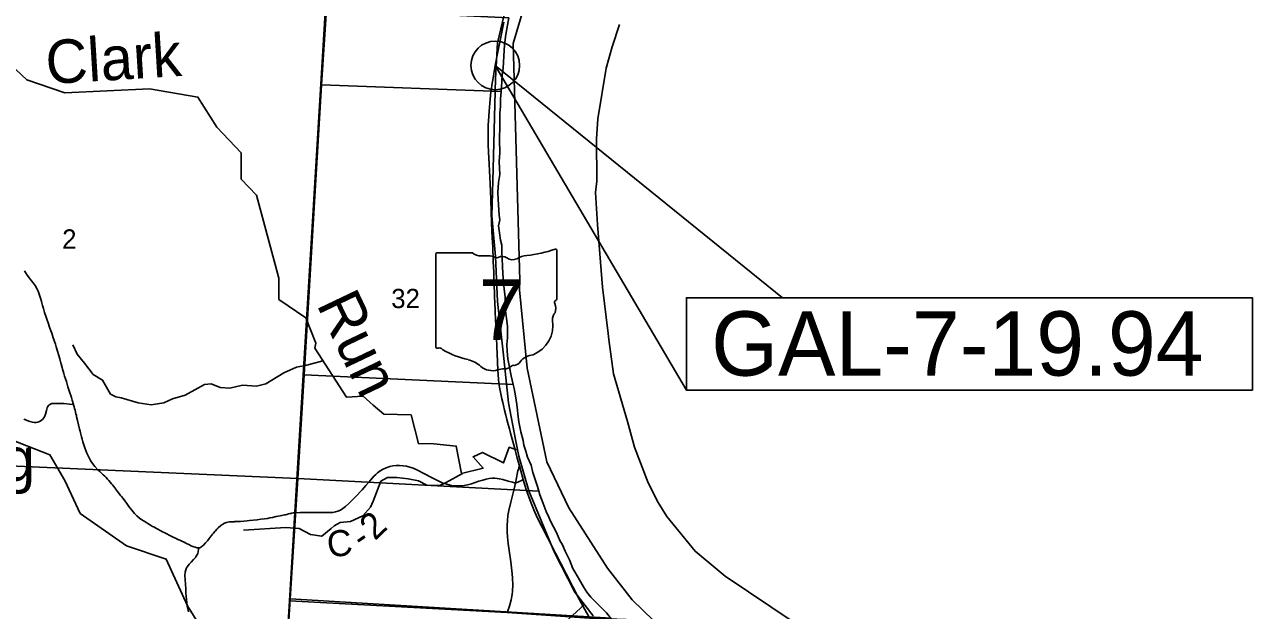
# Model space of a CAD drawing. Extents: x 0 to 34, y 0 to 22.
# Drawn here: x 26.889 to 29.562, y 16.649 to 17.925 of the extents above; entities that cross this region are included whole.
import ezdxf

# ---------------------------------------------------------------- set-up
doc = ezdxf.new("R2010")
doc.units = 0
for name, color, linetype in [('Default', 7, 'Continuous'), ('GM_X_County_Road', 7, 'Continuous'), ('GM_X_County_Road_Text', 7, 'Continuous'), ('GM_X_Interchange_Ramps', 7, 'Continuous'), ('GM_X_Major_River', 7, 'Continuous'), ('GM_X_Minor_River', 7, 'Continuous'), ('GM_X_Minor_River_Text', 7, 'Continuous'), ('GM_X_Section', 7, 'Continuous'), ('GM_X_Section_Text', 7, 'Continuous'), ('GM_X_State_Location', 7, 'Continuous'), ('GM_X_State_Route', 7, 'Continuous'), ('GM_X_State_Shield', 7, 'Continuous'), ('GM_X_Township_Road', 7, 'Continuous'), ('SH_Text', 7, 'Continuous')]:
    doc.layers.add(name, color=color, linetype=linetype)

msp = doc.modelspace()

# ---------------------------------------------------------------- linework, layer by layer
at = {"layer": 'Default'}
for points in [[(27.5436, 17.9511), (27.477, 16.8624), (27.4654, 16.67), (27.9391, 16.6444), (28.1188, 16.6326), (28.2577, 16.6271), (28.2114, 16.6724), (28.1579, 16.7413), (28.0739, 16.8728), (28.0259, 16.9726), (27.9832, 17.1768), (27.9665, 17.3472), (27.9669, 17.3673), (27.9525, 17.8831), (27.9847, 17.9912)], [(26.8866, 15.9536), (26.8953, 15.9537), (26.9051, 15.9532), (26.9173, 15.9519), (26.9205, 15.9516), (26.9254, 15.951), (26.9323, 15.9503), (26.9416, 15.9499), (26.9554, 15.9494), (26.9643, 15.9495), (26.9763, 15.9496), (26.9823, 15.9498), (26.987, 15.951), (26.9903, 15.9525), (26.9911, 15.953), (27.0939, 15.9486), (27.4201, 15.9327), (27.4654, 16.67), (27.477, 16.8624), (27.5436, 17.9511)], [(27.9391, 16.6444), (27.4654, 16.67), (27.4201, 15.9327)]]:
    msp.add_lwpolyline(points, dxfattribs=at)
at = {"layer": 'GM_X_County_Road'}
for points in [[(27.3465, 16.8425), (27.3455, 16.8424), (27.3398, 16.8422), (27.3343, 16.8418), (27.3284, 16.8405), (27.3238, 16.8389), (27.3206, 16.8373), (27.3161, 16.8342), (27.3103, 16.8288), (27.3076, 16.8258), (27.3047, 16.8223), (27.303, 16.8207), (27.3002, 16.8175), (27.2981, 16.8152), (27.2967, 16.8132), (27.2952, 16.8113), (27.2907, 16.8056), (27.2868, 16.8007), (27.2831, 16.7965), (27.2783, 16.7915), (27.2756, 16.789), (27.2739, 16.7877), (27.2724, 16.7867), (27.2701, 16.7858), (27.2681, 16.7855), (27.2667, 16.7853), (27.2647, 16.7855), (27.2623, 16.786), (27.2605, 16.7867), (27.2553, 16.7887), (27.2518, 16.7902), (27.2462, 16.7929), (27.2428, 16.7944), (27.24, 16.7958), (27.2361, 16.7976), (27.2316, 16.7997), (27.227, 16.8019), (27.2225, 16.804), (27.2192, 16.8056), (27.2136, 16.8083), (27.2092, 16.8105), (27.2025, 16.8138), (27.2003, 16.8149), (27.1954, 16.8173), (27.1927, 16.8187), (27.189, 16.8205), (27.1853, 16.8225), (27.1775, 16.8267), (27.1749, 16.8282), (27.1714, 16.8303), (27.1677, 16.8323), (27.1633, 16.8346), (27.1491, 16.8435), (27.1445, 16.8467), (27.1393, 16.8503), (27.1335, 16.855), (27.1281, 16.8602), (27.1221, 16.8674), (27.1185, 16.8721), (27.1156, 16.8758), (27.1112, 16.8818), (27.1071, 16.8876), (27.1034, 16.8928), (27.0997, 16.8973), (27.098, 16.8995), (27.0962, 16.9019), (27.0914, 16.9082), (27.087, 16.9141), (27.0858, 16.9156), (27.0824, 16.9199), (27.0805, 16.9224), (27.0785, 16.9247), (27.0755, 16.9286), (27.0722, 16.9324), (27.0695, 16.9353), (27.0667, 16.9383), (27.0633, 16.9412), (27.0601, 16.9444), (27.0566, 16.9483), (27.0527, 16.9519), (27.0487, 16.9554), (27.0418, 16.9627), (27.0367, 16.969), (27.0325, 16.9753), (27.0292, 16.9813), (27.0245, 16.9916), (27.02, 17.0032), (27.0158, 17.0163), (27.0141, 17.0222), (27.0128, 17.027), (27.0105, 17.036), (27.0096, 17.0396), (27.0086, 17.0438), (27.0042, 17.0625), (27.0023, 17.0709), (27.0017, 17.0733), (27.0007, 17.0775), (26.9988, 17.0853), (26.9978, 17.0889), (26.9968, 17.0924), (26.9956, 17.0966), (26.9953, 17.0978), (26.9924, 17.1072), (26.9908, 17.1126), (26.9893, 17.1173), (26.9875, 17.1232), (26.9856, 17.1292), (26.9834, 17.1363), (26.9817, 17.1416), (26.9799, 17.1475), (26.978, 17.1535), (26.9762, 17.1594), (26.9745, 17.1647), (26.9729, 17.17), (26.9718, 17.1742), (26.9706, 17.1783), (26.9695, 17.1823), (26.9691, 17.1839), (26.9684, 17.1861), (26.968, 17.1877), (26.9654, 17.1966), (26.958, 17.2227), (26.956, 17.229), (26.9542, 17.2345), (26.9526, 17.2391), (26.9514, 17.2426), (26.948, 17.2525), (26.9461, 17.2578), (26.9453, 17.2601), (26.9441, 17.2635), (26.9426, 17.2677), (26.9412, 17.273), (26.9374, 17.2834), (26.9352, 17.2898), (26.9325, 17.298), (26.9301, 17.3066), (26.9282, 17.3132), (26.9257, 17.3219), (26.9235, 17.3292), (26.9208, 17.338), (26.9183, 17.344), (26.916, 17.3489), (26.9118, 17.3563), (26.9079, 17.3621), (26.9042, 17.3667), (26.8999, 17.3723), (26.8948, 17.379), (26.8908, 17.3848), (26.8887, 17.3883)], [(27.9573, 16.926), (27.9507, 16.9282), (27.9415, 16.9309), (27.9303, 16.9339), (27.9223, 16.9358), (27.9173, 16.9367), (27.9124, 16.9372), (27.907, 16.9371), (27.9005, 16.9365), (27.8937, 16.935), (27.8865, 16.9331), (27.8775, 16.9303), (27.8619, 16.9248), (27.853, 16.9223), (27.8459, 16.9209), (27.8385, 16.9205), (27.8315, 16.9203), (27.8229, 16.9208), (27.8156, 16.922), (27.8084, 16.924), (27.7981, 16.9272), (27.7908, 16.9303), (27.7803, 16.9355), (27.7538, 16.9497), (27.7484, 16.9525), (27.7426, 16.9556), (27.7348, 16.9587), (27.7278, 16.961), (27.7203, 16.9631), (27.7129, 16.9641), (27.7047, 16.9648), (27.6977, 16.9647), (27.6908, 16.9638), (27.6841, 16.9623), (27.6763, 16.9597), (27.6695, 16.9567), (27.663, 16.953), (27.6569, 16.9488), (27.6532, 16.9454), (27.6494, 16.9412), (27.6427, 16.9338), (27.6376, 16.928), (27.6318, 16.9215), (27.6237, 16.9121), (27.6196, 16.9075), (27.6138, 16.9011), (27.6092, 16.8965), (27.6042, 16.8913), (27.5994, 16.8865), (27.5946, 16.8817), (27.5875, 16.8754), (27.5818, 16.8708), (27.5765, 16.8676), (27.5711, 16.8652), (27.5657, 16.8637), (27.5599, 16.8627), (27.5523, 16.8625), (27.5451, 16.8624), (27.5302, 16.8627), (27.5228, 16.8626), (27.5136, 16.8626), (27.5081, 16.8627), (27.4988, 16.8625), (27.4938, 16.8625), (27.4889, 16.8624), (27.4772, 16.8619)], [(27.4772, 16.8619), (27.4761, 16.8618), (27.4733, 16.8616), (27.4709, 16.8611), (27.4687, 16.8606), (27.4662, 16.8601), (27.4633, 16.8593), (27.4598, 16.8584), (27.4568, 16.8576), (27.4544, 16.857), (27.4517, 16.8565), (27.4483, 16.8557), (27.4452, 16.855), (27.4367, 16.8534), (27.4288, 16.8518), (27.423, 16.8507), (27.4176, 16.8497), (27.4109, 16.8488), (27.4029, 16.8478), (27.3949, 16.8468), (27.3789, 16.8448), (27.3733, 16.8441), (27.3665, 16.8436), (27.3587, 16.8431), (27.3516, 16.8426), (27.3465, 16.8425)], [(27.2459, 16.6462), (27.245, 16.6496), (27.2441, 16.6533), (27.2437, 16.6547), (27.2433, 16.6564), (27.243, 16.6586), (27.2427, 16.661), (27.242, 16.6664), (27.2413, 16.6736), (27.2408, 16.6796), (27.2403, 16.6867), (27.2397, 16.6962), (27.2384, 16.7164), (27.2381, 16.7256), (27.2385, 16.7323), (27.2396, 16.7376), (27.2412, 16.7418), (27.2433, 16.7452), (27.2469, 16.7497), (27.2513, 16.7543), (27.2567, 16.7598), (27.2588, 16.7623), (27.2607, 16.7646), (27.2627, 16.7676), (27.2642, 16.7699), (27.2658, 16.7734), (27.267, 16.7775), (27.2678, 16.7819), (27.2681, 16.7855)]]:
    msp.add_lwpolyline(points, dxfattribs=at)
at = {"layer": 'GM_X_Interchange_Ramps'}
msp.add_lwpolyline([(27.966, 16.9638), (27.9646, 16.9596), (27.9638, 16.9568), (27.9628, 16.9531), (27.962, 16.9493), (27.9573, 16.926)], dxfattribs=at)
at = {"layer": 'GM_X_Major_River'}
for points in [[(27.9438, 17.9919), (27.9185, 17.8844), (27.9143, 17.8073), (27.909, 17.6107), (27.9064, 17.5078), (27.914, 17.4197), (27.9185, 17.3214), (27.9307, 17.2114), (27.9425, 17.1009), (27.9575, 17.0216), (27.9649, 16.9852), (27.9863, 16.9098), (28.0146, 16.8416), (28.0417, 16.7771), (28.0866, 16.6892), (28.1269, 16.6378)], [(28.1345, 17.5835), (28.1341, 17.6757), (28.1366, 17.719), (28.155, 17.8299), (28.1677, 17.8763), (28.1838, 17.9246)], [(28.5643, 16.6232), (28.4142, 16.724), (28.3486, 16.778), (28.2867, 16.8537), (28.2681, 16.884), (28.246, 16.9268), (28.2169, 17.0049), (28.2012, 17.0602), (28.1709, 17.1645), (28.1608, 17.2389), (28.1592, 17.2521), (28.1467, 17.3527), (28.1364, 17.489), (28.1315, 17.5588), (28.1345, 17.5835)]]:
    msp.add_lwpolyline(points, dxfattribs=at)
at = {"layer": 'GM_X_Minor_River'}
for points in [[(27.9596, 16.9987), (27.9438, 17.0046), (27.9317, 16.9704), (27.8859, 16.9931), (27.8651, 16.9834), (27.8874, 16.959), (27.8402, 16.9471), (27.8287, 17.007), (27.7797, 17.0119), (27.7463, 17.0124), (27.7303, 17.0748), (27.671, 17.0762), (27.6476, 17.0957), (27.6257, 17.1157), (27.5897, 17.1134), (27.5207, 17.2199), (27.5232, 17.2313), (27.5012, 17.2865), (27.4426, 17.3262), (27.4424, 17.3725), (27.3941, 17.5528), (27.3602, 17.5881), (27.3602, 17.6455), (27.3075, 17.7015), (27.2664, 17.7665), (27.1606, 17.7845), (26.9766, 17.7756), (26.8939, 17.8041), (26.8093, 17.8831)], [(27.5385, 17.1925), (27.5033, 17.1832), (27.4806, 17.179), (27.4536, 17.1664), (27.4142, 17.1424), (27.3937, 17.1371), (27.363, 17.1393), (27.3357, 17.1332), (27.3145, 17.1347), (27.2948, 17.1423), (27.2804, 17.1411), (27.2387, 17.1179), (27.2106, 17.1095), (27.1924, 17.1011), (27.1644, 17.0969), (27.1363, 17.1011), (27.0992, 17.112), (27.0878, 17.1139), (27.0757, 17.12), (27.0586, 17.1508), (27.0385, 17.1626), (27.0192, 17.1876), (27.0037, 17.2074), (26.9942, 17.2275)], [(27.3244, 16.5292), (27.2434, 16.659), (27.1972, 16.7611), (27.1111, 16.7896), (27.0099, 16.8604), (26.9767, 16.9319), (26.9441, 16.9877), (26.8224, 17.0349)], [(27.8419, 16.9476), (27.8053, 16.9268), (27.7932, 16.9211), (27.7648, 16.9222), (27.7466, 16.931), (27.7238, 16.9359), (27.6992, 16.9389), (27.6791, 16.9385), (27.6643, 16.9305), (27.648, 16.8871), (27.6419, 16.8738), (27.6252, 16.8548), (27.5987, 16.8426), (27.5756, 16.8403), (27.5631, 16.8331), (27.5566, 16.8277), (27.5358, 16.8106), (27.5111, 16.8148), (27.4865, 16.8277), (27.4573, 16.8295), (27.3656, 16.8241)], [(28.1078, 16.6622), (27.9757, 16.5411)]]:
    msp.add_lwpolyline(points, dxfattribs=at)
at = {"layer": 'GM_X_Section'}
for points in [[(26.4949, 18.0036), (27.546, 17.9583), (27.5355, 17.7931), (27.4974, 17.1618), (27.484, 16.9363), (26.4248, 16.9831)], [(27.9429, 17.9393), (27.9398, 17.9229), (27.9365, 17.9029), (27.9339, 17.8805), (27.9321, 17.8555), (27.9307, 17.8297), (27.9288, 17.8149), (27.9278, 17.8001), (27.9267, 17.7785), (27.5355, 17.7931), (27.546, 17.9583)], [(27.5355, 17.7931), (27.9267, 17.7785), (27.9252, 17.7626), (27.9249, 17.7467), (27.9234, 17.7319), (27.9232, 17.7058), (27.9229, 17.6736), (27.9234, 17.6455), (27.9219, 17.6262), (27.9235, 17.5978), (27.9209, 17.5804), (27.9191, 17.5599), (27.9199, 17.5436), (27.9219, 17.5095), (27.9235, 17.4997), (27.9209, 17.4864), (27.9225, 17.4709), (27.9248, 17.455), (27.9275, 17.4444), (27.9275, 17.4307), (27.9292, 17.3985), (27.93, 17.3822), (27.9327, 17.3485), (27.9351, 17.3319), (27.9348, 17.308), (27.9379, 17.2849), (27.9398, 17.2682), (27.9399, 17.2428), (27.9385, 17.2284), (27.9393, 17.2133), (27.9412, 17.197), (27.9447, 17.1788), (27.9482, 17.1599), (27.9523, 17.1413), (27.4974, 17.1618)], [(27.9523, 17.1413), (27.9543, 17.1323), (27.9574, 17.116), (27.9601, 17.0974), (27.9621, 17.0853), (27.9625, 17.0762), (27.9648, 17.0599), (27.9694, 17.0383), (27.974, 17.0194), (27.9756, 17.0092), (27.9798, 16.9956), (27.984, 16.9831), (27.9913, 16.9657), (27.9955, 16.9498), (28.0012, 16.932), (28.0058, 16.9187), (28.0084, 16.9087), (27.484, 16.9363), (27.4974, 17.1618)], [(27.484, 16.9363), (27.4673, 16.6748), (27.4216, 15.9328), (26.3734, 15.9843), (26.3613, 15.9846), (26.4248, 16.9831)], [(28.0084, 16.9087), (28.0104, 16.901), (28.0177, 16.8817), (28.0246, 16.8646), (28.0303, 16.8521), (28.0341, 16.8438), (28.0467, 16.8189), (28.0544, 16.8015), (28.0597, 16.792), (28.0658, 16.7784), (28.0719, 16.7655), (28.0753, 16.7591), (28.0822, 16.7406), (28.0864, 16.733), (28.0967, 16.7156), (28.1055, 16.7009), (28.1131, 16.6888), (28.1215, 16.6782), (28.1344, 16.6653), (28.1553, 16.6442), (28.1618, 16.637), (28.1661, 16.6321), (27.4673, 16.6748), (27.484, 16.9363)], [(28.1661, 16.6321), (28.1717, 16.6257), (28.1922, 16.6049), (28.2108, 16.5868), (28.2199, 16.58), (28.2302, 16.5721), (28.2405, 16.5645), (28.2518, 16.5578), (28.2598, 16.5498), (28.2678, 16.5389), (28.278, 16.5301), (27.7753, 16.5515), (27.7478, 16.3019), (27.731, 16.1489), (27.7176, 16.0274), (27.7054, 15.9168), (27.4216, 15.9328), (27.4673, 16.6748)]]:
    msp.add_lwpolyline(points, close=True, dxfattribs=at)
at = {"layer": 'GM_X_State_Route'}
for points in [[(27.966, 16.9638), (27.9615, 16.9804), (27.9566, 16.999), (27.9469, 17.035), (27.9443, 17.0446), (27.9418, 17.0542), (27.939, 17.0649), (27.9365, 17.0745), (27.9337, 17.0853), (27.9312, 17.0955), (27.9297, 17.1022), (27.9279, 17.11), (27.9249, 17.124), (27.9229, 17.135), (27.9216, 17.1437), (27.9206, 17.153), (27.9193, 17.1722), (27.9174, 17.2082), (27.9168, 17.2224), (27.9161, 17.2441), (27.9153, 17.2615), (27.9143, 17.2807), (27.9132, 17.3012), (27.9126, 17.3198), (27.9122, 17.3316), (27.9111, 17.3639), (27.9107, 17.3745), (27.9102, 17.3862), (27.9097, 17.3974), (27.9092, 17.408), (27.9087, 17.4216), (27.9084, 17.4297), (27.908, 17.4402), (27.907, 17.4607), (27.9064, 17.4743), (27.9048, 17.5159), (27.9038, 17.5444), (27.9022, 17.578), (27.9016, 17.5922), (27.8995, 17.6344), (27.899, 17.6468), (27.8983, 17.6636), (27.8982, 17.6761), (27.8982, 17.6846), (27.8982, 17.6941), (27.8984, 17.7065), (27.8987, 17.714), (27.8999, 17.7357), (27.9014, 17.7537), (27.903, 17.7704), (27.9038, 17.7778), (27.9043, 17.7809), (27.9069, 17.7969), (27.9096, 17.8122), (27.9104, 17.8177), (27.9135, 17.8355), (27.9191, 17.8654), (27.9251, 17.8934), (27.9319, 17.9294)], [(28.119, 16.6321), (28.1119, 16.6445), (28.1046, 16.6581), (28.0963, 16.6741), (28.0682, 16.7288), (28.0445, 16.774), (28.0276, 16.8065), (28.0153, 16.8303), (28.005, 16.8515), (27.9976, 16.868), (27.9914, 16.8829), (27.9863, 16.8963), (27.9809, 16.9122), (27.9757, 16.9289), (27.9742, 16.9341), (27.9689, 16.9528), (27.966, 16.9638)], [(27.94, 16.6458), (27.9417, 16.6507), (27.9435, 16.656), (27.9451, 16.6612), (27.9478, 16.6726), (27.95, 16.684), (27.9508, 16.6911), (27.9515, 16.7051), (27.9513, 16.7192), (27.9504, 16.7287), (27.9474, 16.7547), (27.9438, 16.7797), (27.9418, 16.795), (27.9401, 16.8096), (27.9394, 16.8201), (27.9392, 16.8345), (27.9398, 16.8445), (27.9412, 16.8558), (27.9432, 16.8671), (27.9475, 16.8852), (27.9538, 16.9111), (27.9573, 16.926), (27.964, 16.9291), (27.9704, 16.9322), (27.9742, 16.9341)]]:
    msp.add_lwpolyline(points, dxfattribs=at)
at = {"layer": 'GM_X_State_Shield'}
for p, q in [((27.8636, 17.4273), (27.7864, 17.4273)), ((28.0475, 17.3276), (28.0475, 17.4322)), ((27.7838, 17.4238), (27.7838, 17.2237)), ((28.0474, 17.3276), (28.0475, 17.3276))]:
    msp.add_line(p, q, dxfattribs=at)
for centre, radius, start, end in [((27.7868, 17.4243), 0.00305, 98.1301, 188.1301), ((27.882, 17.4505), 0.0296, 231.6195, 271.1119), ((27.9535, 17.7001), 0.2796, 275.8445, 288.9065), ((28.0445, 17.4327), 0.00294, 351.8621, 97.738), ((27.8918, 17.3149), 0.1064, 80.4867, 94.9883), ((27.916, 17.4253), 0.00855, 219.7921, 297.1024), ((27.9285, 17.4022), 0.0178, 54.4667, 119.1411), ((27.9515, 17.4339), 0.0214, 233.8562, 294.8282), ((27.9892, 17.3662), 0.0563, 97.3462, 120.7689), ((28.0468, 17.3199), 0.00454, 107.944, 210.337), ((28.0443, 17.3271), 0.00314, 289.6038, 7.7341), ((28.058, 17.2837), 0.0198, 136.8065, 186.9296), ((28.0179, 17.3066), 0.0273, 340.033, 23.6496), ((27.9692, 17.2704), 0.0699, 292.3089, 8.9858), ((27.7869, 17.2233), 0.00308, 171.9584, 258.3066), ((27.7873, 17.2438), 0.0235, 267.339, 280.6039), ((27.7921, 17.2122), 0.00848, 29.7484, 93.2717), ((27.8992, 17.392), 0.2019, 240.4129, 257.1985), ((27.839, 17.1338), 0.0632, 47.1842, 75.836), ((27.9502, 17.2043), 0.0226, 282.8732, 323.2771), ((27.9987, 17.1675), 0.0383, 94.4031, 142.5768), ((27.9073, 17.2112), 0.0401, 230.7004, 286.2918), ((27.9305, 17.142), 0.0329, 85.6951, 111.2099), ((27.9334, 17.1962), 0.0214, 268.777, 315.5493), ((27.9527, 17.1768), 0.00601, 65.7517, 132.6484)]:
    msp.add_arc(centre, radius, start, end, dxfattribs=at)
at = {"layer": 'GM_X_Township_Road'}
msp.add_lwpolyline([(26.8872, 17.0657), (26.9005, 17.0605), (26.9059, 17.0589), (26.9097, 17.0584), (26.9141, 17.0585), (26.9179, 17.0592), (26.9215, 17.0605), (26.9248, 17.0625), (26.9277, 17.0649), (26.9306, 17.0683), (26.9328, 17.0721), (26.9345, 17.0762), (26.9367, 17.0847), (26.9383, 17.0906), (26.9395, 17.0933), (26.9409, 17.0952), (26.9426, 17.0969), (26.9452, 17.0984), (26.9486, 17.0994), (26.9529, 17.0999), (26.9615, 17.1), (26.9684, 17.0998), (26.9744, 17.0995), (26.9867, 17.0985), (26.9953, 17.0978)], dxfattribs=at)
at = {"layer": 'SH_Text'}
msp.add_lwpolyline([(28.2577, 16.6271), (28.2114, 16.6724), (28.1579, 16.7413), (28.0739, 16.8728), (28.0259, 16.9726), (27.9832, 17.1768), (27.9665, 17.3472), (27.9669, 17.3673), (27.9525, 17.8831), (27.9847, 17.9912)], dxfattribs=at)
for points in [[(28.3295, 17.129), (27.9135, 17.8355), (28.5386, 17.3299), (28.3295, 17.3299)], [(28.3295, 17.3299), (29.5617, 17.3299), (29.5617, 17.129), (28.3295, 17.129)]]:
    msp.add_lwpolyline(points, close=True, dxfattribs=at)
msp.add_circle((27.9135, 17.8355), 0.053, dxfattribs=at)

# ---------------------------------------------------------------- texts
at = {"layer": 'GM_X_County_Road_Text'}
for s, rotation, p in [('2', 43.8461, (27.6515, 16.7996)), ('C', 7.704, (27.5512, 16.7637)), ('-', 33.7753, (27.6236, 16.7798))]:
    msp.add_text(s, height=0.0568, rotation=rotation, dxfattribs=at).set_placement(p)
at = {"layer": 'GM_X_Minor_River_Text'}
for s, rotation, p in [('Clark', 3.5111, (26.9376, 17.7947)), ('Run', 295.5123, (27.5234, 17.316)), ('Long', 0.5112, (26.6304, 16.9288))]:
    msp.add_text(s, height=0.0947, rotation=rotation, dxfattribs=at).set_placement(p)
at = {"layer": 'GM_X_Section_Text'}
for s, height, p in [('2', 0.0419, (26.9708, 17.4368)), ('32', 0.04186, (27.6871, 17.3073))]:
    msp.add_text(s, height=height, rotation=0, dxfattribs=at).set_placement(p)
at = {"layer": 'GM_X_State_Location'}
msp.add_text('7', height=0.000189, rotation=0, dxfattribs=at).set_placement((27.8841, 17.2967))
for s in ['s', 'r']:
    msp.add_text(s, height=0.000189, dxfattribs=at).set_placement((27.9127, 17.3105))
at = {"layer": 'GM_X_State_Shield'}
msp.add_text('7', height=0.1318, dxfattribs=at).set_placement((27.8779, 17.2378))
at = {"layer": 'SH_Text'}
msp.add_text('GAL-7-19.94', height=0.14, dxfattribs=at).set_placement((28.3835, 17.1603))

doc.saveas('drawing.dxf')
